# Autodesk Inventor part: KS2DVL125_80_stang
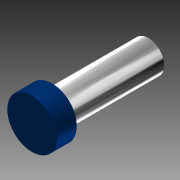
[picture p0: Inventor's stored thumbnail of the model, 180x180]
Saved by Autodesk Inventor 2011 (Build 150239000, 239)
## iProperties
Created: 2010-11
Document SubType Name: Modeling
Designer: TB
Mass: 161.233 g
Surface Area: 236.814 cm^2
Volume: 161.233 cm^3
Density: 1 g/cm^3
Author: TB
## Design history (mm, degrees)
sketch "Sketch2"
  geometry: L1 (-35, -3)-(-35, 3) reference; L2 (-35, -9)-(-35, 9) reference; L3 (-35, 40)-(-328, 40); L4 (-328, 40)-(-328, 0); L5 (-328, 0)-(-35, 0); L6 (-35, 0)-(-35, 40); L7 (-328, 40)-(-276, 40); L8 (-276, 40)-(-276, 62.5); L9 (-276, 62.5)-(-328, 62.5); L10 (-328, 62.5)-(-328, 40); 1 further point
  constraints: 16 end point, 4 parallel, 2 horizontal, 2 perpendicular, 1 midpoint
  dimensions: "Dia" = 80 diameter of L3 L5; "d3" = 293 distance of L3.start L3.end (computed from Slaglengde, Forlengelse_rør); "StempelDia" = 125 diameter of L9 L5; "StempelLengde" = 52 distance of L8.end L9.end
revolve "Revolution1" sketch "Sketch2" stored, may be unused: angle "d6" = 90 deg
fillet "Fillet1" dims "d7" = 2
sketch "Sketch3"
  geometry: L1 (-328, -60.5)-(-328, 60.5) reference; L2 (-328, 0)-(-328.01, 0); L3 (-328, 0)-(-328, 0.01); A1 r 0.01 centre (-328, 0) between (-328, 0.01) and (-328.01, 0); 1 further point
  constraints: 4 end point, 2 point on circle, 1 centre point, 1 midpoint, 1 perpendicular, 1 point on line
  dimensions: "d8" = 0.01 distance of L2.start L2.end; "d9" = 0.01 distance of L2.start L3.end (= d8); "d10" = 0.01 radius of A1 (= d8)
revolve "Revolution2" sketch "Sketch3" stored, may be unused: angle "d11" = 90 deg
body "Solid1"
node "Projected Loop2"
other parameters: "Forlengelse_rør" = 0
